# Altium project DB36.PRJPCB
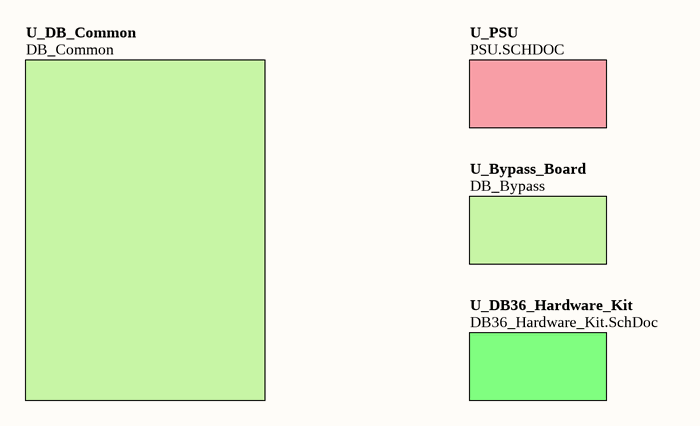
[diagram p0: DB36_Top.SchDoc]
ProjectAddress1: L3, 12A Rodborough Road; ProjectAddress2: Frenchs Forest; ProjectAddress3: NSW 2086; ProjectAddress4: Australia; ProjectAssyNum: D-820-0010; ProjectOrganization: Altium Limited; ProjectRevision: 01; ProjectTitle: DB36 - Daughter Board Virtex4; ProjectTotalSheets: 23
9 sheets, 100 parts. Net scope: hierarchical (ports join the sheet entries above them; power ports are global).
Board files: DB36.PcbDoc, DB36_Panel.PcbDoc
Sheets:
  DB36_Top.SchDoc
    U_PSU = PSU.SCHDOC
    U_DB36_Hardware_Kit = DB36_Hardware_Kit.SchDoc
  DEVICES.SchDoc
    U_FPGA = FPGA.SCHDOC
      U_FPGA_Power = FPGA_NonIO.SchDoc
      U_Bypass_3V3 = Bypass_FPGA_3V3.SchDoc
      U_Bypass_2V5 = Bypass_FPGA_2V5.SCHDOC
      U_Bypass_1V2 = Bypass_FPGA_1V2.SCHDOC

## Sheet DB36_Top.SchDoc: DB36 Top Level
size A4; Organization: Altium Limited.; Address1: Level 3, 12a Rodborough Rd; Address2: Frenchs Forest 2086; Address3: NSW; Address4: AUSTRALIA; DocumentNumber: 1; SheetNumber: 2; SheetTotal: 23

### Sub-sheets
U_Bypass_Board = DB_Bypass (file not in this document): no entries
U_DB36_Hardware_Kit = DB36_Hardware_Kit.SchDoc: no entries
U_DB_Common = DB_Common (file not in this document): no entries
U_PSU = PSU.SCHDOC: no entries

## Sheet PSU.SCHDOC: Power Supplies
size A4; Organization: Altium Limited.; Address1: Level 3, 12a Rodborough Rd; Address2: Frenchs Forest 2086; Address3: NSW; Address4: AUSTRALIA; DocumentNumber: 10; SheetNumber: 10; SheetTotal: 23
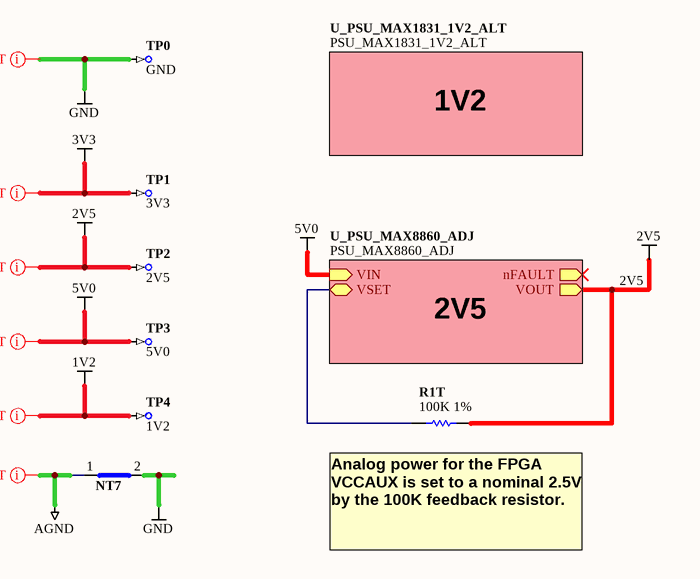
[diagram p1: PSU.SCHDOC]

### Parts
NT7  Net Tie SMT2  [NETTIE-SMT2-8X8]  (value not drawn)  (net tie, no BOM)
R1T  100K 1%  [RESC1005-STAR]
TP0  GND  [TestPin]  (no BOM)
TP1  3V3  [TestPin]  (no BOM)
TP2  2V5  [TestPin]  (no BOM)
TP3  5V0  [TestPin]  (no BOM)
TP4  1V2  [TestPin]  (no BOM)

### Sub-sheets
U_PSU_MAX1831_1V2_ALT = PSU_MAX1831_1V2_ALT (file not in this document): no entries
U_PSU_MAX8860_ADJ = PSU_MAX8860_ADJ (file not in this document): nFAULT (out), VIN (in), VOUT (out), VSET (bidir)

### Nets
1V2: TP4.1
2V5: R1T.2 TP2.1 ; sheet U_PSU_MAX8860_ADJ/VOUT
3V3: TP1.1
5V0: TP3.1 ; sheet U_PSU_MAX8860_ADJ/VIN
AGND: NT7.1(Net1)
GND: NT7.2(Net2) TP0.1
NetR1T_1: R1T.1 ; sheet U_PSU_MAX8860_ADJ/VSET

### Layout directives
net class PWRNET: 1V2, 2V5, 3V3, 5V0, AGND, GND

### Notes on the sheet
- 1V2
- 2V5
- (near R1T) Analog power for the FPGA VCCAUX is set to a nominal 2.5V by the 100K feedback resistor.

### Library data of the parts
NT7 = D-002-0002: Net-Tie, Surface Mount, 2 x 0.4mm x 0.2mm SMT Pads - For 0.2mm Track
R1T = D-100-0132: Resistor, 100K 1% 0402 (1005); Power Rating: 63 mW
TP0-TP4 = D-006-0000: Test Point, PCB Mount with Silkscreen Box

## Sheet DB36_Hardware_Kit.SchDoc: DB36 Hardware Kit
size A4; Organization: Altium Limited.; Address1: Level 3, 12a Rodborough Rd; Address2: Frenchs Forest 2086; Address3: NSW; Address4: AUSTRALIA; DocumentNumber: 9; SheetNumber: 9; SheetTotal: 23
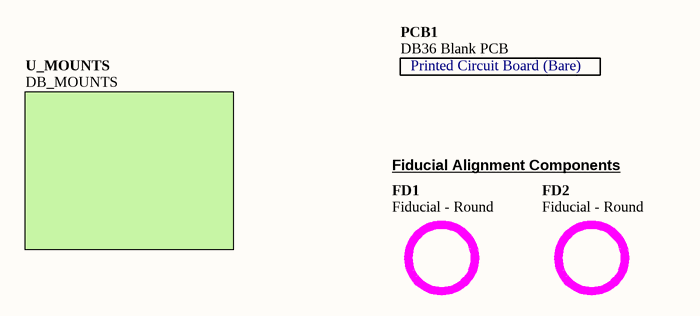
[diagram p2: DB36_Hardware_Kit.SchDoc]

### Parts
FD1  Fiducial - Round  [FIDUCIAL ROUND]
FD2  Fiducial - Round  [FIDUCIAL ROUND]
PCB1  DB36 Blank PCB  [DB36 Blank PCB]

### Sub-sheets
U_MOUNTS = DB_MOUNTS (file not in this document): no entries

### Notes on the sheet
- Fiducial Alignment Components

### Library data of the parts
FD1 FD2 = D-000-0005: Fiducial - Round 1.5mm Top-Bottom
PCB1 = D-810-0010: DB36 Blank PCB - Daughter Board Xilinx Virtex4 XC4VLX25FF668; ProjectPath: DB36.PrjPCB

## Sheet DEVICES.SchDoc: FPGA, LEDs and SRAM Memory
size A4; Organization: Altium Limited.; Address1: Level 3, 12a Rodborough Rd; Address2: Frenchs Forest 2086; Address3: NSW; Address4: AUSTRALIA; DocumentNumber: 2; SheetNumber: 3; SheetTotal: 23
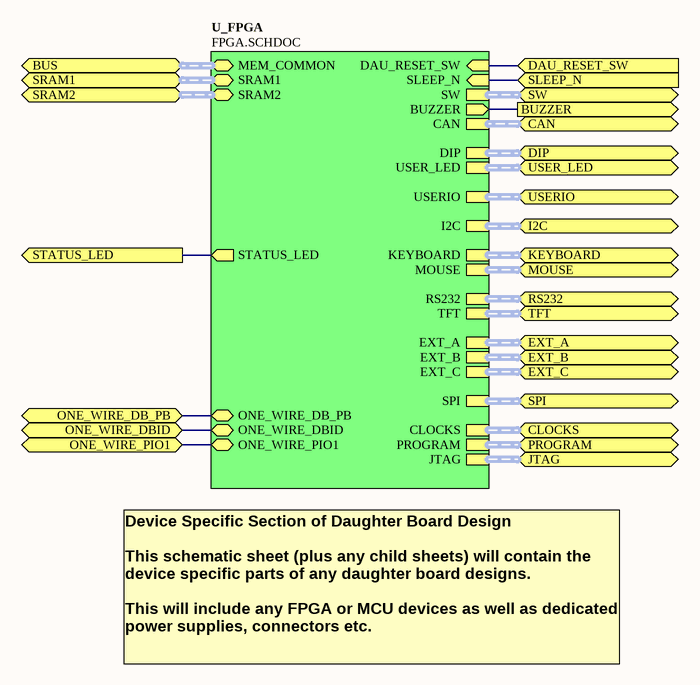
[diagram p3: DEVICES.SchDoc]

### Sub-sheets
U_FPGA = FPGA.SCHDOC: SRAM1 (harness SRAM-256Kx16), SRAM2 (harness SRAM-256Kx16), MEM_COMMON (harness HOSTMEMORY), DAU_RESET_SW (in), BUZZER (out), ONE_WIRE_DBID (bidir), ONE_WIRE_DB_PB (bidir), ONE_WIRE_PIO1 (bidir), JTAG (harness HardSoft_JTAG), SW (harness SW5), DIP (harness SW8), USERIO (harness IO36), EXT_A (harness PBIO), EXT_B (harness PBIO), EXT_C (harness PBIO), USER_LED (harness LED8), SPI (harness DAU_SPI), I2C (harness I2C), CAN (harness CAN_INT), RS232 (harness RS232_INT), KEYBOARD (harness PS2), MOUSE (harness PS2), TFT (harness DAU_TFT), PROGRAM (harness DAU_CTRL), CLOCKS (harness DAU_CLK), STATUS_LED (out), SLEEP_N (in)

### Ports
BUS (harness HOSTMEMORY), BUZZER (out), CAN, CLOCKS, DAU_RESET_SW (in), DIP, EXT_A, EXT_B, EXT_C, I2C, JTAG, KEYBOARD, MOUSE, ONE_WIRE_DB_PB (bidir), ONE_WIRE_DBID (bidir), ONE_WIRE_PIO1 (bidir), PROGRAM, RS232, SLEEP_N (in), SPI, SRAM1, SRAM2 (harness SRAM-256Kx16), STATUS_LED (out), SW, TFT, USER_LED, USERIO

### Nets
BUZZER: port BUZZER, sheet U_FPGA/BUZZER
DAU_RESET_SW: port DAU_RESET_SW, sheet U_FPGA/DAU_RESET_SW
ONE_WIRE_DB_PB: port ONE_WIRE_DB_PB, sheet U_FPGA/ONE_WIRE_DB_PB
ONE_WIRE_DBID: port ONE_WIRE_DBID, sheet U_FPGA/ONE_WIRE_DBID
ONE_WIRE_PIO1: port ONE_WIRE_PIO1, sheet U_FPGA/ONE_WIRE_PIO1
SLEEP_N: port SLEEP_N, sheet U_FPGA/SLEEP_N
STATUS_LED: port STATUS_LED, sheet U_FPGA/STATUS_LED

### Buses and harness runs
harness port BUS = sheet U_FPGA/MEM_COMMON
harness port CAN = sheet U_FPGA/CAN
harness port CLOCKS = sheet U_FPGA/CLOCKS
harness port DIP = sheet U_FPGA/DIP
harness port EXT_A = sheet U_FPGA/EXT_A
harness port EXT_B = sheet U_FPGA/EXT_B
harness port EXT_C = sheet U_FPGA/EXT_C
harness port I2C = sheet U_FPGA/I2C
harness port JTAG = sheet U_FPGA/JTAG
harness port KEYBOARD = sheet U_FPGA/KEYBOARD
harness port MOUSE = sheet U_FPGA/MOUSE
harness port PROGRAM = sheet U_FPGA/PROGRAM
harness port RS232 = sheet U_FPGA/RS232
harness port SPI = sheet U_FPGA/SPI
harness port SRAM1 = sheet U_FPGA/SRAM1
harness port SRAM2 = sheet U_FPGA/SRAM2
harness port SW = sheet U_FPGA/SW
harness port TFT = sheet U_FPGA/TFT
harness port USER_LED = sheet U_FPGA/USER_LED
harness port USERIO = sheet U_FPGA/USERIO

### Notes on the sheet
- Device Specific Section of Daughter Board Design
  This schematic sheet (plus any child sheets) will contain the device specific parts of any daughter board designs.
  This will include any FPGA or MCU devices as well as dedicated power supplies, connectors etc.

## Sheet FPGA.SCHDOC: FPGA
size A2; Organization: Altium Limited.; Address1: Level 3, 12a Rodborough Rd; Address2: Frenchs Forest 2086; Address3: NSW; Address4: AUSTRALIA; DocumentNumber: 3; SheetNumber: 4; SheetTotal: 23; PageSetup: Record=PageOptions|CenterHorizontal=True|CenterVertical=True|PrintScale=0.71|XCorrection=1.00|YCorrection=1.00|PrintKind=0|BorderSize=5000000|LeftOffset=0|BottomOffset=0|Orientation=2|PaperLength=4199|PaperWidth=2969|Scale=100|PaperSource=7|PrintQuality=600|MediaType=1|DitherType=10|PaperKind=A3 (297 x 420 mm)|PrintScaleMode=1
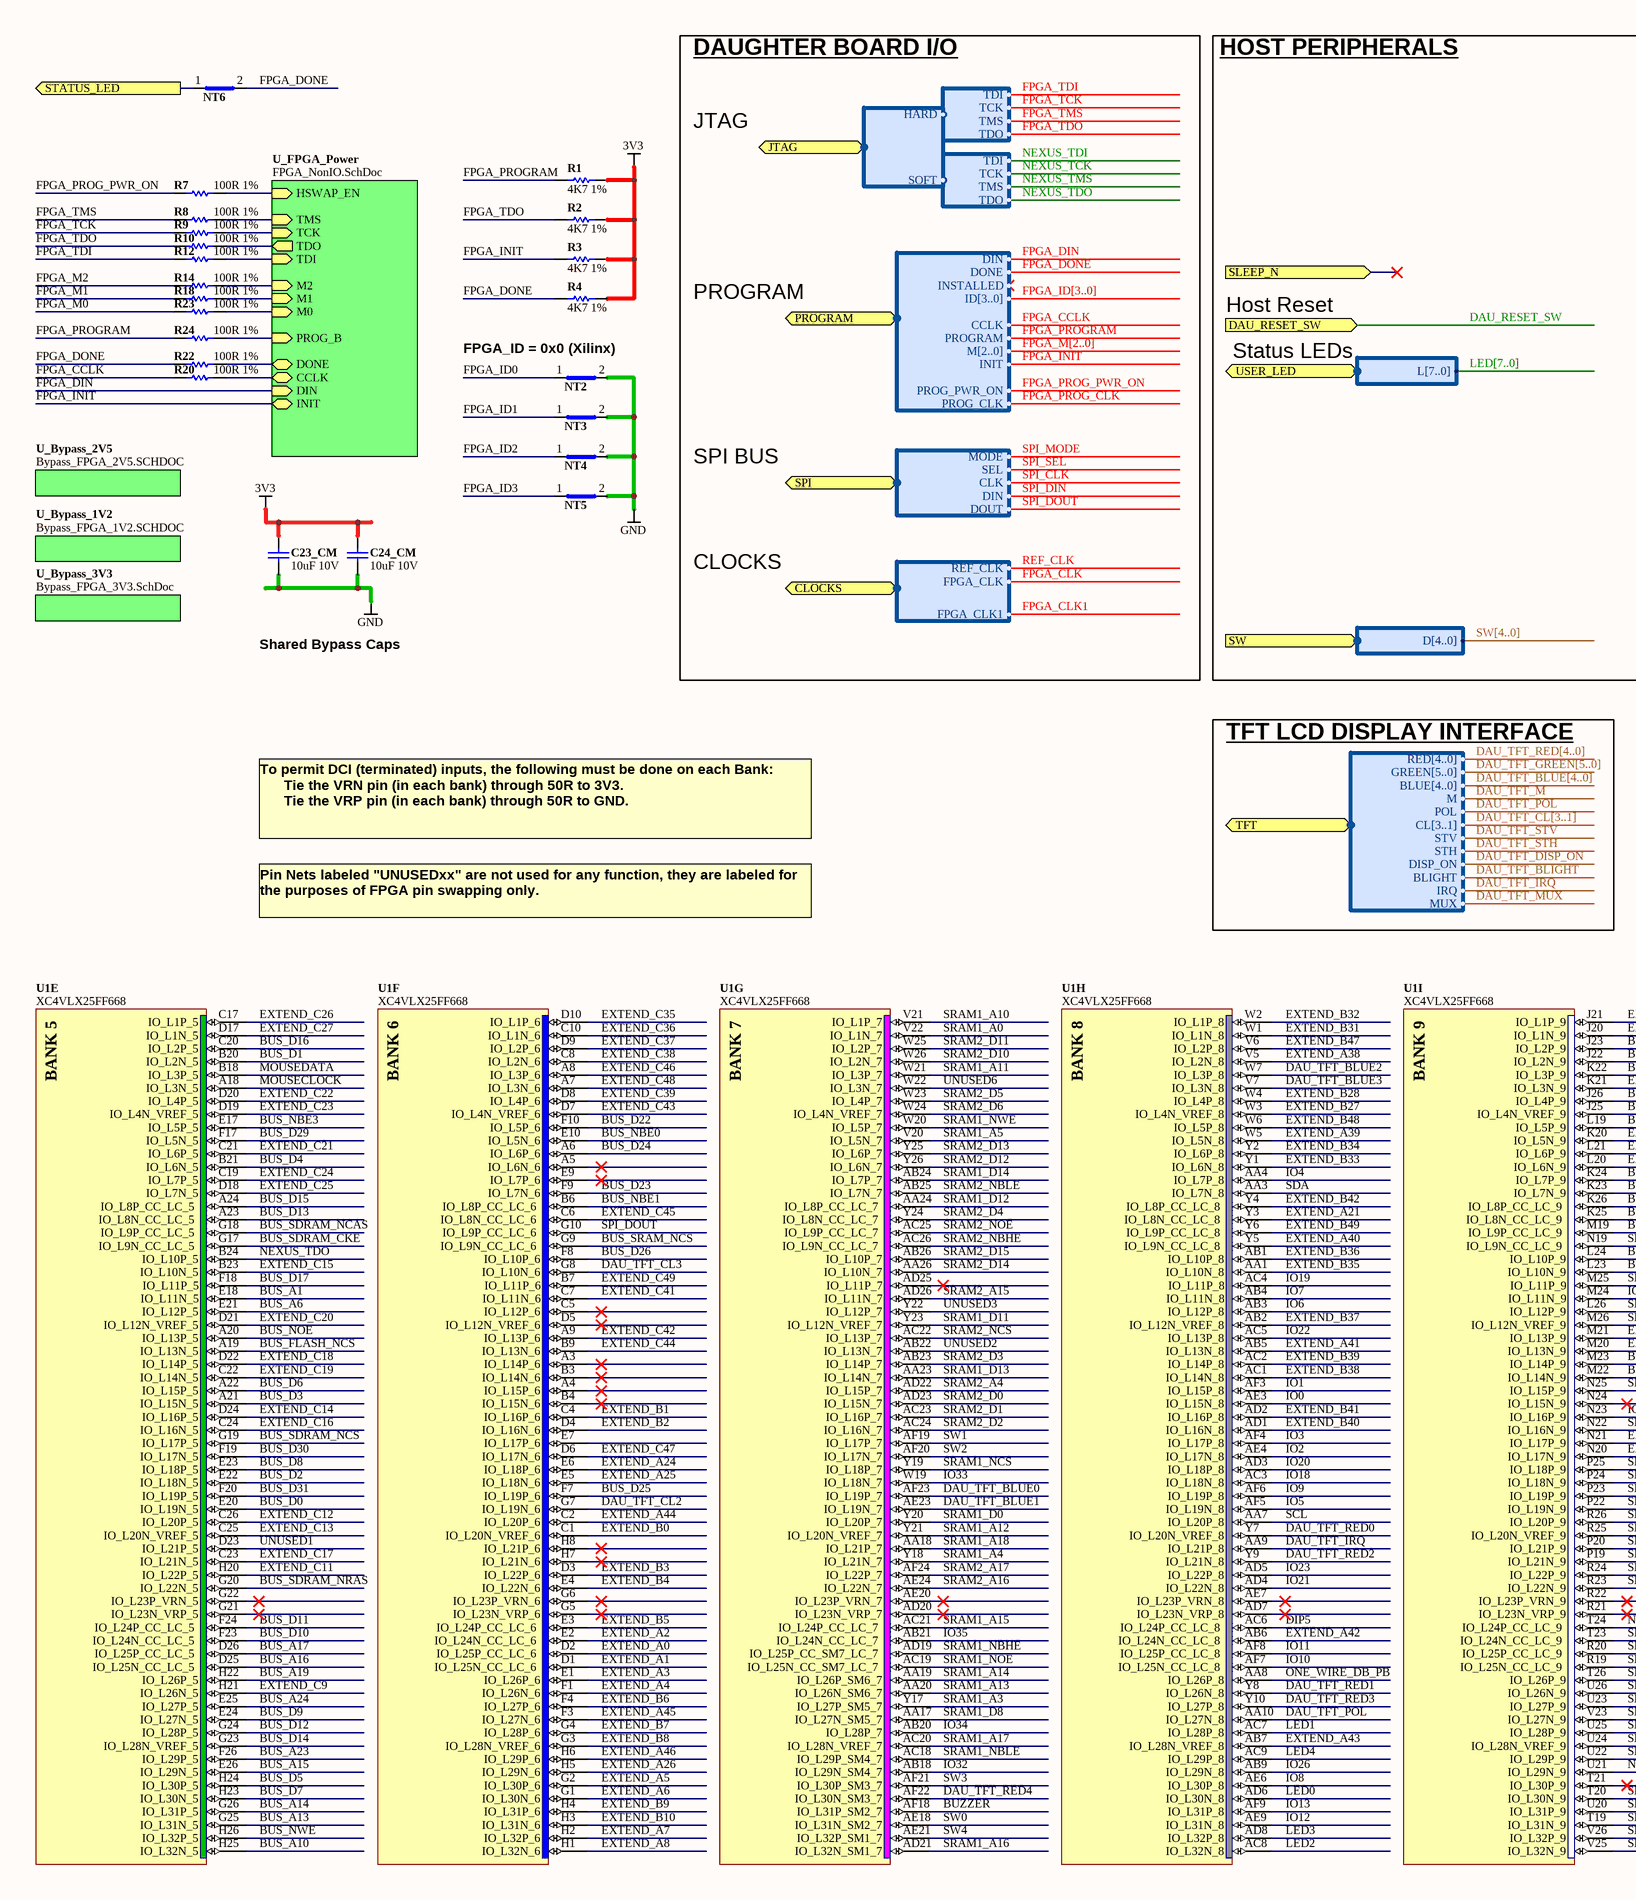
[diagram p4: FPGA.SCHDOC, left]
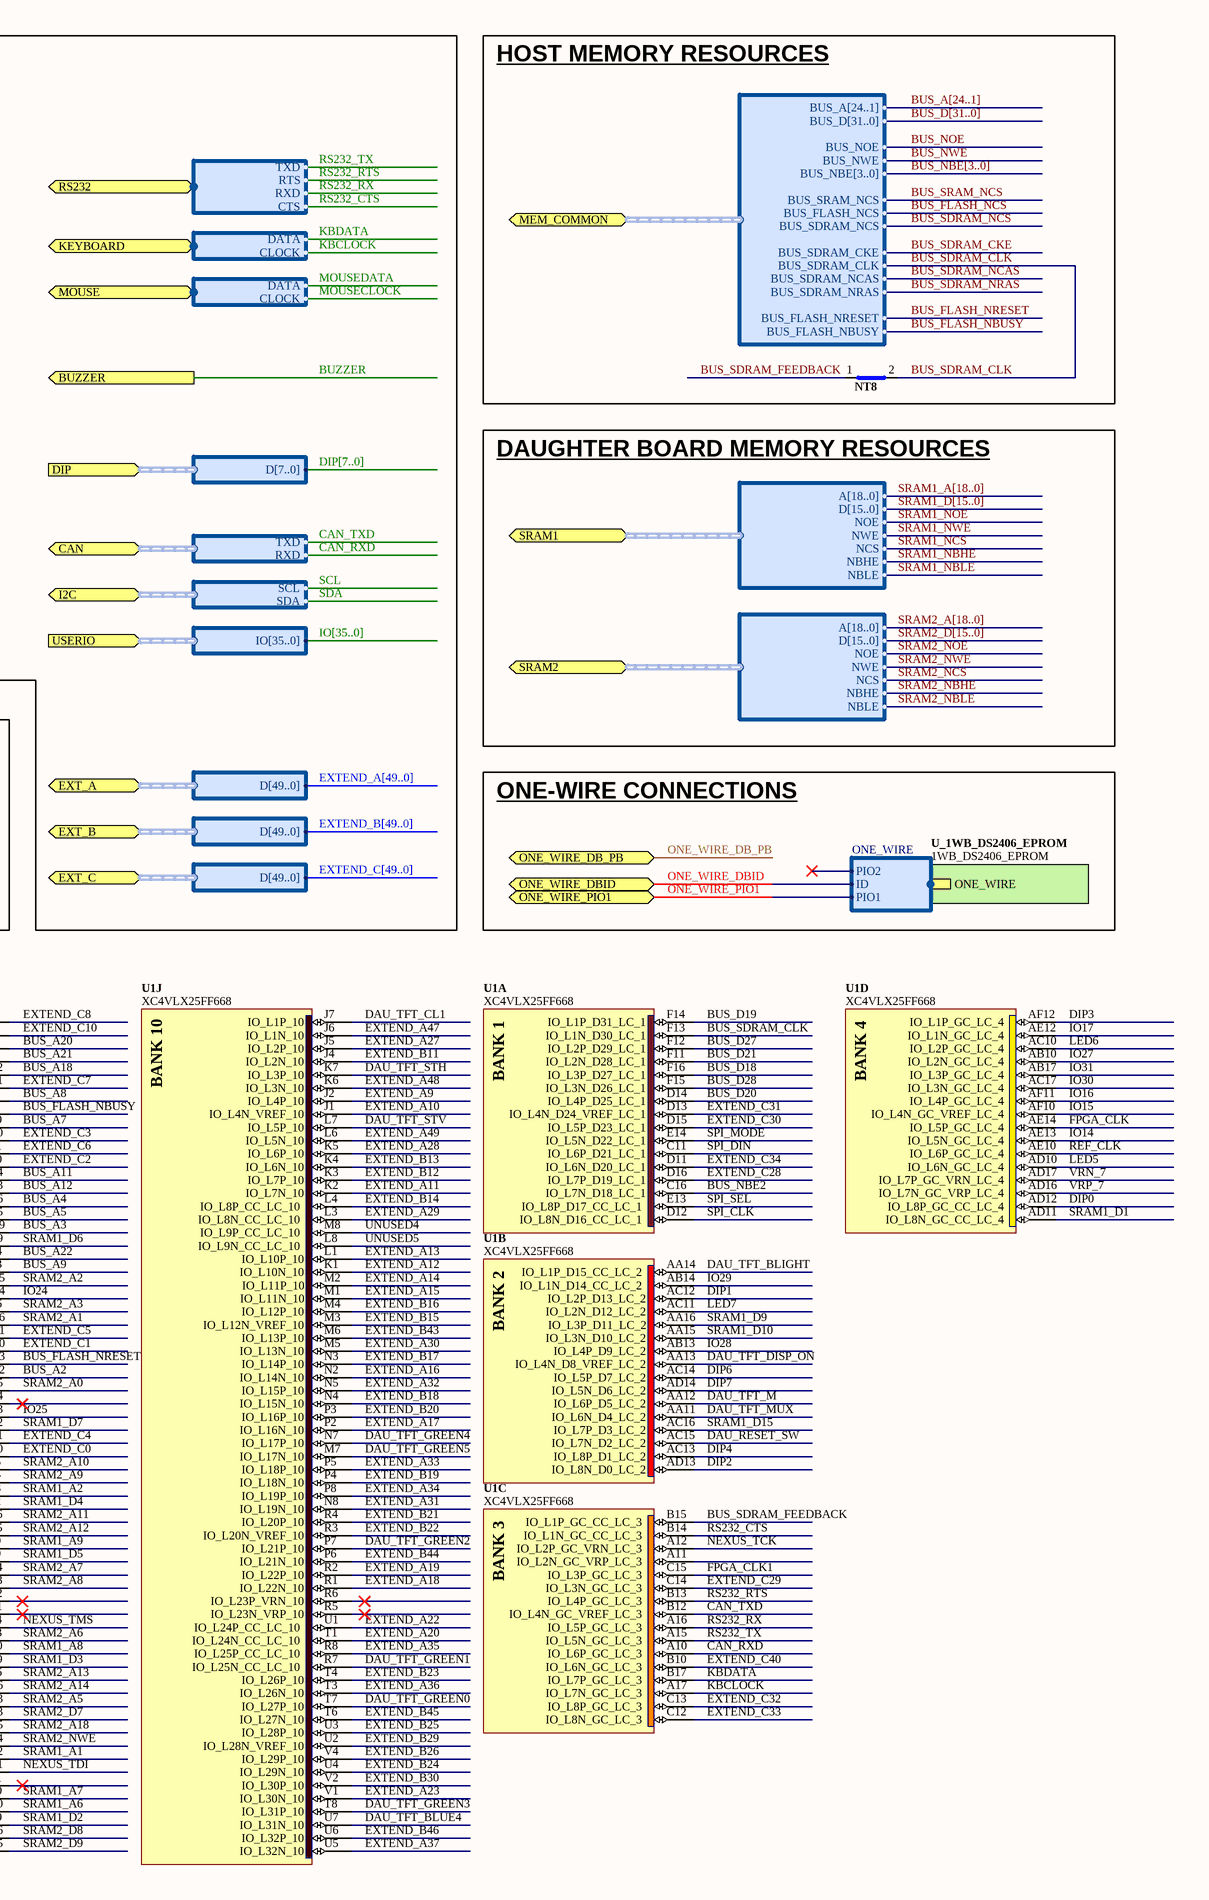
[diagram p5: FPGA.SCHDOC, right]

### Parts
C23_CM  10uF 10V  [CAPC2012-STAR]
C24_CM  10uF 10V  [CAPC2012-STAR]
NT2  Net Tie SMT2  [NETTIE-SMT2-8X8]  (value not drawn)  (net tie, no BOM)
NT3  Net Tie SMT2  [NETTIE-SMT2-8X8]  (value not drawn)  (net tie, no BOM)
NT4  Net Tie SMT2  [NETTIE-SMT2-8X8]  (value not drawn)  (net tie, no BOM)
NT5  Net Tie SMT2  [NETTIE-SMT2-8X8]  (value not drawn)  (net tie, no BOM)
NT6  Net Tie SMT2  [NETTIE-SMT2-8X8]  (value not drawn)  (net tie, no BOM)
NT8  Net Tie SMT2  [NETTIE-SMT2-8X8]  (value not drawn)  (net tie, no BOM)
R1  4K7 1%  [RESC1005-STAR]
R2  4K7 1%  [RESC1005-STAR]
R3  4K7 1%  [RESC1005-STAR]
R4  4K7 1%  [RESC1005-STAR]
R7  100R 1%  [RESC1005-STAR]
R8  100R 1%  [RESC1005-STAR]
R9  100R 1%  [RESC1005-STAR]
R10  100R 1%  [RESC1005-STAR]
R12  100R 1%  [RESC1005-STAR]
R14  100R 1%  [RESC1005-STAR]
R18  100R 1%  [RESC1005-STAR]
R20  100R 1%  [RESC1005-STAR]
R22  100R 1%  [RESC1005-STAR]
R23  100R 1%  [RESC1005-STAR]
R24  100R 1%  [RESC1005-STAR]
U1  XC4VLX25FF668  [XC4VLX25-10FF668C]  (parts A,B,C,D,E,F,G,H,I,J of 14)

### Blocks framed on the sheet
HOST MEMORY RESOURCES: NT8

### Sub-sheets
U_1WB_DS2406_EPROM = 1WB_DS2406_EPROM (file not in this document): ONE_WIRE (harness ONE_WIRE)
U_Bypass_1V2 = Bypass_FPGA_1V2.SCHDOC: no entries
U_Bypass_2V5 = Bypass_FPGA_2V5.SCHDOC: no entries
U_Bypass_3V3 = Bypass_FPGA_3V3.SchDoc: no entries
U_FPGA_Power = FPGA_NonIO.SchDoc: TMS (in), DONE (bidir), M1 (in), CCLK (bidir), M0 (in), M2 (in), TCK (in), HSWAP_EN (in), TDI (in), PROG_B (in), TDO (out), DIN (in), INIT (bidir)

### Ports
BUZZER (out), CAN (harness CAN_INT), CLOCKS (harness DAU_CLK), DAU_RESET_SW (in), DIP (harness SW8), EXT_A (harness PBIO), EXT_B (harness PBIO), EXT_C (harness PBIO), I2C (harness I2C), JTAG (harness HARDSOFT_JTAG), KEYBOARD (harness PS2), MEM_COMMON (harness HOSTMEMORY), MOUSE (harness PS2), ONE_WIRE_DB_PB (bidir), ONE_WIRE_DBID (bidir), ONE_WIRE_PIO1 (bidir), PROGRAM (harness DAU_CTRL), RS232 (harness RS232_INT), SLEEP_N (in), SPI (harness DAU_SPI), SRAM1 (harness SRAM-256Kx16), SRAM2 (harness SRAM-256Kx16), STATUS_LED (out), SW (harness SW5), TFT (harness DAU_TFT), USER_LED (harness LED8), USERIO (harness IO36)

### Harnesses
ONE_WIRE: ID, PIO1, PIO2
SRAM-256Kx16: A[18..0], D[15..0], NCS, NWE, NOE, NBHE, NBLE
HOSTMEMORY: BUS_A[24..1], BUS_D[31..0], BUS_NOE, BUS_NWE, BUS_NBE[3..0], BUS_SRAM_NCS, BUS_FLASH_NCS, BUS_SDRAM_NCS, BUS_SDRAM_CKE, BUS_SDRAM_CLK, BUS_SDRAM_NCAS, BUS_SDRAM_NRAS, BUS_FLASH_NRESET, BUS_FLASH_NBUSY
DAU_CLK: REF_CLK, FPGA_CLK, FPGA_CLK1
DAU_SPI: MODE, SEL, CLK, DIN, DOUT
DAU_CTRL: DIN, DONE, INSTALLED, ID[3..0], CCLK, PROGRAM, M[2..0], INIT, PROG_PWR_ON, PROG_CLK
JTAG: TMS, TDO, TDI, TCK
HARDSOFT_JTAG: HARD, SOFT
LED8: L[7..0]
SW5: D[4..0]
DAU_TFT: RED[4..0], GREEN[5..0], BLUE[4..0], M, POL, CL[3..1], STV, STH, DISP_ON, BLIGHT, IRQ, MUX
PS2: DATA, CLOCK
RS232_INT: RXD, TXD, RTS, CTS
IO36: IO[35..0]
SW8: D[7..0]
CAN_INT: TXD, RXD
I2C: SCL, SDA
PBIO: D[49..0]

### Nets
3V3: C23_CM.1 C24_CM.1 R1.2 R2.2 R3.2 R4.2
GND: C23_CM.2 C24_CM.2 NT2.2(Net2) NT3.2(Net2) NT4.2(Net2) NT5.2(Net2)
BUS_A1: U1.E18(IO_L11N_5)
BUS_A2: U1.M22(IO_L14N_9)
BUS_A3: U1.M19(IO_L9P_CC_LC_9)
BUS_A4: U1.K26(IO_L8P_CC_LC_9)
BUS_A5: U1.K25(IO_L8N_CC_LC_9)
BUS_A6: U1.E21(IO_L12P_5)
BUS_A7: U1.L19(IO_L5P_9)
BUS_A8: U1.J26(IO_L4P_9)
BUS_A9: U1.L23(IO_L10N_9)
BUS_A10: U1.H25(IO_L32N_5)
BUS_A11: U1.K24(IO_L7P_9)
BUS_A12: U1.K23(IO_L7N_9)
BUS_A13: U1.G25(IO_L31N_5)
BUS_A14: U1.G26(IO_L31P_5)
BUS_A15: U1.E26(IO_L29N_5)
BUS_A16: U1.D25(IO_L25N_CC_LC_5)
BUS_A17: U1.D26(IO_L25P_CC_LC_5)
BUS_A18: U1.K22(IO_L3P_9)
BUS_A19: U1.H22(IO_L26P_5)
BUS_A20: U1.J23(IO_L2P_9)
BUS_A21: U1.J22(IO_L2N_9)
BUS_A22: U1.L24(IO_L10P_9)
BUS_A23: U1.F26(IO_L29P_5)
BUS_A24: U1.E25(IO_L27P_5)
BUS_D0: U1.E20(IO_L19N_5)
BUS_D1: U1.B20(IO_L2N_5)
BUS_D2: U1.E22(IO_L18N_5)
BUS_D3: U1.A21(IO_L15N_5)
BUS_D4: U1.B21(IO_L6N_5)
BUS_D5: U1.H24(IO_L30P_5)
BUS_D6: U1.A22(IO_L15P_5)
BUS_D7: U1.H23(IO_L30N_5)
BUS_D8: U1.E23(IO_L18P_5)
BUS_D9: U1.E24(IO_L27N_5)
BUS_D10: U1.F23(IO_L24N_CC_LC_5)
BUS_D11: U1.F24(IO_L24P_CC_LC_5)
BUS_D12: U1.G24(IO_L28P_5)
BUS_D13: U1.A23(IO_L8N_CC_LC_5)
BUS_D14: U1.G23(IO_L28N_VREF_5)
BUS_D15: U1.A24(IO_L8P_CC_LC_5)
BUS_D16: U1.C20(IO_L2P_5)
BUS_D17: U1.F18(IO_L11P_5)
BUS_D18: U1.F16(IO_L3P_D27_LC_1)
BUS_D19: U1.F14(IO_L1P_D31_LC_1)
BUS_D20: U1.D14(IO_L4P_D25_LC_1)
BUS_D21: U1.F11(IO_L2N_D28_LC_1)
BUS_D22: U1.F10(IO_L5P_6)
BUS_D23: U1.F9(IO_L7N_6)
BUS_D24: U1.A6(IO_L6P_6)
BUS_D25: U1.F7(IO_L19P_6)
BUS_D26: U1.F8(IO_L10P_6)
BUS_D27: U1.F12(IO_L2P_D29_LC_1)
BUS_D28: U1.F15(IO_L3N_D26_LC_1)
BUS_D29: U1.F17(IO_L5N_5)
BUS_D30: U1.F19(IO_L17N_5)
BUS_D31: U1.F20(IO_L19P_5)
BUS_FLASH_NBUSY: U1.J25(IO_L4N_VREF_9) ; port MEM_COMMON.BUS_FLASH_NBUSY
BUS_FLASH_NCS: U1.A19(IO_L13N_5) ; port MEM_COMMON.BUS_FLASH_NCS
BUS_FLASH_NRESET: U1.M23(IO_L14P_9) ; port MEM_COMMON.BUS_FLASH_NRESET
BUS_NBE0: U1.E10(IO_L5N_6)
BUS_NBE1: U1.B6(IO_L8P_CC_LC_6)
BUS_NBE2: U1.C16(IO_L7N_D18_LC_1)
BUS_NBE3: U1.E17(IO_L5P_5)
BUS_NOE: U1.A20(IO_L13P_5) ; port MEM_COMMON.BUS_NOE
BUS_NWE: U1.H26(IO_L32P_5) ; port MEM_COMMON.BUS_NWE
BUS_SDRAM_CKE: U1.G17(IO_L9N_CC_LC_5) ; port MEM_COMMON.BUS_SDRAM_CKE
BUS_SDRAM_CLK: NT8.2(Net2) U1.F13(IO_L1N_D30_LC_1) ; port MEM_COMMON.BUS_SDRAM_CLK
BUS_SDRAM_FEEDBACK: NT8.1(Net1) U1.B15(IO_L1P_GC_CC_LC_3)
BUS_SDRAM_NCAS: U1.G18(IO_L9P_CC_LC_5) ; port MEM_COMMON.BUS_SDRAM_NCAS
BUS_SDRAM_NCS: U1.G19(IO_L17P_5) ; port MEM_COMMON.BUS_SDRAM_NCS
BUS_SDRAM_NRAS: U1.G20(IO_L22N_5) ; port MEM_COMMON.BUS_SDRAM_NRAS
BUS_SRAM_NCS: U1.G9(IO_L9N_CC_LC_6) ; port MEM_COMMON.BUS_SRAM_NCS
BUZZER: U1.AF18(IO_L31P_SM2_7) ; port BUZZER
CAN_RXD: U1.A10(IO_L6P_GC_LC_3) ; port CAN.RXD
CAN_TXD: U1.B12(IO_L4N_GC_VREF_LC_3) ; port CAN.TXD
CCLK: R20.2 ; sheet U_FPGA_Power/CCLK
DAU_RESET_SW: U1.AC15(IO_L7N_D2_LC_2) ; port DAU_RESET_SW
DAU_TFT_BLIGHT: U1.AA14(IO_L1P_D15_CC_LC_2) ; port TFT.BLIGHT
DAU_TFT_BLUE0: U1.AF23(IO_L19P_7)
DAU_TFT_BLUE1: U1.AE23(IO_L19N_7)
DAU_TFT_BLUE2: U1.W7(IO_L3P_8)
DAU_TFT_BLUE3: U1.V7(IO_L3N_8)
DAU_TFT_BLUE4: U1.U7(IO_L31N_10)
DAU_TFT_CL1: U1.J7(IO_L1P_10)
DAU_TFT_CL2: U1.G7(IO_L19N_6)
DAU_TFT_CL3: U1.G8(IO_L10N_6)
DAU_TFT_DISP_ON: U1.AA13(IO_L4N_D8_VREF_LC_2) ; port TFT.DISP_ON
DAU_TFT_GREEN0: U1.T7(IO_L27P_10)
DAU_TFT_GREEN1: U1.R7(IO_L25N_CC_LC_10)
DAU_TFT_GREEN2: U1.P7(IO_L21P_10)
DAU_TFT_GREEN3: U1.T8(IO_L31P_10)
DAU_TFT_GREEN4: U1.N7(IO_L17P_10)
DAU_TFT_GREEN5: U1.M7(IO_L17N_10)
DAU_TFT_IRQ: U1.AA9(IO_L21P_8) ; port TFT.IRQ
DAU_TFT_M: U1.AA12(IO_L6P_D5_LC_2) ; port TFT.M
DAU_TFT_MUX: U1.AA11(IO_L6N_D4_LC_2) ; port TFT.MUX
DAU_TFT_POL: U1.AA10(IO_L27N_8) ; port TFT.POL
DAU_TFT_RED0: U1.Y7(IO_L20N_VREF_8)
DAU_TFT_RED1: U1.Y8(IO_L26N_8)
DAU_TFT_RED2: U1.Y9(IO_L21N_8)
DAU_TFT_RED3: U1.Y10(IO_L27P_8)
DAU_TFT_RED4: U1.AF22(IO_L30N_SM3_7)
DAU_TFT_STH: U1.K7(IO_L3P_10) ; port TFT.STH
DAU_TFT_STV: U1.L7(IO_L5P_10) ; port TFT.STV
DIP0: U1.AD12(IO_L8P_GC_CC_LC_4)
DIP1: U1.AC12(IO_L2P_D13_LC_2)
DIP2: U1.AD13(IO_L8N_D0_LC_2)
DIP3: U1.AF12(IO_L1P_GC_LC_4)
DIP4: U1.AC13(IO_L8P_D1_LC_2)
DIP5: U1.AC6(IO_L24P_CC_LC_8)
DIP6: U1.AC14(IO_L5P_D7_LC_2)
DIP7: U1.AD14(IO_L5N_D6_LC_2)
DONE: R22.2 ; sheet U_FPGA_Power/DONE
EXTEND_A0: U1.D2(IO_L25P_CC_LC_6)
EXTEND_A1: U1.D1(IO_L25N_CC_LC_6)
EXTEND_A2: U1.E2(IO_L24N_CC_LC_6)
EXTEND_A3: U1.E1(IO_L26P_6)
EXTEND_A4: U1.F1(IO_L26N_6)
EXTEND_A5: U1.G2(IO_L30P_6)
EXTEND_A6: U1.G1(IO_L30N_6)
EXTEND_A7: U1.H2(IO_L32P_6)
EXTEND_A8: U1.H1(IO_L32N_6)
EXTEND_A9: U1.J2(IO_L4P_10)
EXTEND_A10: U1.J1(IO_L4N_VREF_10)
EXTEND_A11: U1.K2(IO_L7N_10)
EXTEND_A12: U1.K1(IO_L10N_10)
EXTEND_A13: U1.L1(IO_L10P_10)
EXTEND_A14: U1.M2(IO_L11P_10)
EXTEND_A15: U1.M1(IO_L11N_10)
EXTEND_A16: U1.N2(IO_L14N_10)
EXTEND_A17: U1.P2(IO_L16N_10)
EXTEND_A18: U1.R1(IO_L22N_10)
EXTEND_A19: U1.R2(IO_L22P_10)
EXTEND_A20: U1.T1(IO_L24N_CC_LC_10)
EXTEND_A21: U1.Y3(IO_L8N_CC_LC_8)
EXTEND_A22: U1.U1(IO_L24P_CC_LC_10)
EXTEND_A23: U1.V1(IO_L30N_10)
EXTEND_A24: U1.E6(IO_L18P_6)
EXTEND_A25: U1.E5(IO_L18N_6)
EXTEND_A26: U1.H5(IO_L29N_6)
EXTEND_A27: U1.J5(IO_L2P_10)
EXTEND_A28: U1.K5(IO_L6P_10)
EXTEND_A29: U1.L3(IO_L8N_CC_LC_10)
EXTEND_A30: U1.M5(IO_L13N_10)
EXTEND_A31: U1.N8(IO_L19N_10)
EXTEND_A32: U1.N5(IO_L15P_10)
EXTEND_A33: U1.P5(IO_L18P_10)
EXTEND_A34: U1.P8(IO_L19P_10)
EXTEND_A35: U1.R8(IO_L25P_CC_LC_10)
EXTEND_A36: U1.T3(IO_L26N_10)
EXTEND_A37: U1.U5(IO_L32N_10)
EXTEND_A38: U1.V5(IO_L2N_8)
EXTEND_A39: U1.W5(IO_L5N_8)
EXTEND_A40: U1.Y5(IO_L9N_CC_LC_8)
EXTEND_A41: U1.AB5(IO_L13N_8)
EXTEND_A42: U1.AB6(IO_L24N_CC_LC_8)
EXTEND_A43: U1.AB7(IO_L28N_VREF_8)
EXTEND_A44: U1.C2(IO_L20P_6)
EXTEND_A45: U1.F3(IO_L27N_6)
EXTEND_A46: U1.H6(IO_L29P_6)
EXTEND_A47: U1.J6(IO_L1N_10)
EXTEND_A48: U1.K6(IO_L3N_10)
EXTEND_A49: U1.L6(IO_L5N_10)
EXTEND_B0: U1.C1(IO_L20N_VREF_6)
EXTEND_B1: U1.C4(IO_L16P_6)
EXTEND_B2: U1.D4(IO_L16N_6)
EXTEND_B3: U1.D3(IO_L22P_6)
EXTEND_B4: U1.E4(IO_L22N_6)
EXTEND_B5: U1.E3(IO_L24P_CC_LC_6)
EXTEND_B6: U1.F4(IO_L27P_6)
EXTEND_B7: U1.G4(IO_L28P_6)
EXTEND_B8: U1.G3(IO_L28N_VREF_6)
EXTEND_B9: U1.H4(IO_L31P_6)
EXTEND_B10: U1.H3(IO_L31N_6)
EXTEND_B11: U1.J4(IO_L2N_10)
EXTEND_B12: U1.K3(IO_L7P_10)
EXTEND_B13: U1.K4(IO_L6N_10)
EXTEND_B14: U1.L4(IO_L8P_CC_LC_10)
EXTEND_B15: U1.M3(IO_L12N_VREF_10)
EXTEND_B16: U1.M4(IO_L12P_10)
EXTEND_B17: U1.N3(IO_L14P_10)
EXTEND_B18: U1.N4(IO_L15N_10)
EXTEND_B19: U1.P4(IO_L18N_10)
EXTEND_B20: U1.P3(IO_L16P_10)
EXTEND_B21: U1.R4(IO_L20P_10)
EXTEND_B22: U1.R3(IO_L20N_VREF_10)
EXTEND_B23: U1.T4(IO_L26P_10)
EXTEND_B24: U1.U4(IO_L29N_10)
EXTEND_B25: U1.U3(IO_L28P_10)
EXTEND_B26: U1.V4(IO_L29P_10)
EXTEND_B27: U1.W3(IO_L4N_VREF_8)
EXTEND_B28: U1.W4(IO_L4P_8)
EXTEND_B29: U1.U2(IO_L28N_VREF_10)
EXTEND_B30: U1.V2(IO_L30P_10)
EXTEND_B31: U1.W1(IO_L1N_8)
EXTEND_B32: U1.W2(IO_L1P_8)
EXTEND_B33: U1.Y1(IO_L6N_8)
EXTEND_B34: U1.Y2(IO_L6P_8)
EXTEND_B35: U1.AA1(IO_L10N_8)
EXTEND_B36: U1.AB1(IO_L10P_8)
EXTEND_B37: U1.AB2(IO_L12N_VREF_8)
EXTEND_B38: U1.AC1(IO_L14N_8)
EXTEND_B39: U1.AC2(IO_L14P_8)
EXTEND_B40: U1.AD1(IO_L16N_8)
EXTEND_B41: U1.AD2(IO_L16P_8)
EXTEND_B42: U1.Y4(IO_L8P_CC_LC_8)
EXTEND_B43: U1.M6(IO_L13P_10)
EXTEND_B44: U1.P6(IO_L21N_10)
EXTEND_B45: U1.T6(IO_L27N_10)
EXTEND_B46: U1.U6(IO_L32P_10)
EXTEND_B47: U1.V6(IO_L2P_8)
EXTEND_B48: U1.W6(IO_L5P_8)
EXTEND_B49: U1.Y6(IO_L9P_CC_LC_8)
EXTEND_C0: U1.N20(IO_L17N_9)
EXTEND_C1: U1.M20(IO_L13N_9)
EXTEND_C2: U1.L20(IO_L6N_9)
EXTEND_C3: U1.K20(IO_L5N_9)
EXTEND_C4: U1.N21(IO_L17P_9)
EXTEND_C5: U1.M21(IO_L13P_9)
EXTEND_C6: U1.L21(IO_L6P_9)
EXTEND_C7: U1.K21(IO_L3N_9)
EXTEND_C8: U1.J21(IO_L1P_9)
EXTEND_C9: U1.H21(IO_L26N_5)
EXTEND_C10: U1.J20(IO_L1N_9)
EXTEND_C11: U1.H20(IO_L22P_5)
EXTEND_C12: U1.C26(IO_L20P_5)
EXTEND_C13: U1.C25(IO_L20N_VREF_5)
EXTEND_C14: U1.D24(IO_L16P_5)
EXTEND_C15: U1.B23(IO_L10N_5)
EXTEND_C16: U1.C24(IO_L16N_5)
EXTEND_C17: U1.C23(IO_L21N_5)
EXTEND_C18: U1.D22(IO_L14P_5)
EXTEND_C19: U1.C22(IO_L14N_5)
EXTEND_C20: U1.D21(IO_L12N_VREF_5)
EXTEND_C21: U1.C21(IO_L6P_5)
EXTEND_C22: U1.D20(IO_L4P_5)
EXTEND_C23: U1.D19(IO_L4N_VREF_5)
EXTEND_C24: U1.C19(IO_L7P_5)
EXTEND_C25: U1.D18(IO_L7N_5)
EXTEND_C26: U1.C17(IO_L1P_5)
EXTEND_C27: U1.D17(IO_L1N_5)
EXTEND_C28: U1.D16(IO_L7P_D19_LC_1)
EXTEND_C29: U1.C14(IO_L3N_GC_LC_3)
EXTEND_C30: U1.D15(IO_L5P_D23_LC_1)
EXTEND_C31: U1.D13(IO_L4N_D24_VREF_LC_1)
EXTEND_C32: U1.C13(IO_L8P_GC_LC_3)
EXTEND_C33: U1.C12(IO_L8N_GC_LC_3)
EXTEND_C34: U1.D11(IO_L6N_D20_LC_1)
EXTEND_C35: U1.D10(IO_L1P_6)
EXTEND_C36: U1.C10(IO_L1N_6)
EXTEND_C37: U1.D9(IO_L2P_6)
EXTEND_C38: U1.C8(IO_L2N_6)
EXTEND_C39: U1.D8(IO_L4P_6)
EXTEND_C40: U1.B10(IO_L6N_GC_LC_3)
EXTEND_C41: U1.C7(IO_L11N_6)
EXTEND_C42: U1.A9(IO_L13P_6)
EXTEND_C43: U1.D7(IO_L4N_VREF_6)
EXTEND_C44: U1.B9(IO_L13N_6)
EXTEND_C45: U1.C6(IO_L8N_CC_LC_6)
EXTEND_C46: U1.A8(IO_L3P_6)
EXTEND_C47: U1.D6(IO_L17N_6)
EXTEND_C48: U1.A7(IO_L3N_6)
EXTEND_C49: U1.B7(IO_L11P_6)
FPGA_CCLK: R20.1 ; port PROGRAM.CCLK
FPGA_CLK: U1.AE14(IO_L5P_GC_LC_4) ; port CLOCKS.FPGA_CLK
FPGA_CLK1: U1.C15(IO_L3P_GC_LC_3) ; port CLOCKS.FPGA_CLK1
FPGA_DIN: sheet U_FPGA_Power/DIN, port PROGRAM.DIN
FPGA_DONE: NT6.2(Net2) R4.1 R22.1 ; port PROGRAM.DONE
FPGA_ID0: NT2.1(Net1)
FPGA_ID1: NT3.1(Net1)
FPGA_ID2: NT4.1(Net1)
FPGA_ID3: NT5.1(Net1)
FPGA_INIT: R3.1 ; sheet U_FPGA_Power/INIT, port PROGRAM.INIT
FPGA_M0: R23.1
FPGA_M1: R18.1
FPGA_M2: R14.1
FPGA_PROG_PWR_ON: R7.1 ; port PROGRAM.PROG_PWR_ON
FPGA_PROGRAM: R1.1 R24.1 ; port PROGRAM.PROGRAM
FPGA_TCK: R9.1 ; harness JTAG.TCK
FPGA_TDI: R12.1 ; harness JTAG.TDI
FPGA_TDO: R2.1 R10.1 ; harness JTAG.TDO
FPGA_TMS: R8.1 ; harness JTAG.TMS
HSWAP_EN: R7.2 ; sheet U_FPGA_Power/HSWAP_EN
IO0: U1.AE3(IO_L15N_8)
IO1: U1.AF3(IO_L15P_8)
IO2: U1.AE4(IO_L17N_8)
IO3: U1.AF4(IO_L17P_8)
IO4: U1.AA4(IO_L7P_8)
IO5: U1.AF5(IO_L19N_8)
IO6: U1.AB3(IO_L12P_8)
IO7: U1.AB4(IO_L11N_8)
IO8: U1.AE6(IO_L30P_8)
IO9: U1.AF6(IO_L19P_8)
IO10: U1.AF7(IO_L25N_CC_LC_8)
IO11: U1.AF8(IO_L25P_CC_LC_8)
IO12: U1.AE9(IO_L31N_8)
IO13: U1.AF9(IO_L31P_8)
IO14: U1.AE13(IO_L5N_GC_LC_4)
IO15: U1.AF10(IO_L4N_GC_VREF_LC_4)
IO16: U1.AF11(IO_L4P_GC_LC_4)
IO17: U1.AE12(IO_L1N_GC_LC_4)
IO18: U1.AC3(IO_L18N_8)
IO19: U1.AC4(IO_L11P_8)
IO20: U1.AD3(IO_L18P_8)
IO21: U1.AD4(IO_L22N_8)
IO22: U1.AC5(IO_L13P_8)
IO23: U1.AD5(IO_L22P_8)
IO24: U1.M24(IO_L11N_9)
IO25: U1.N23(IO_L16P_9)
IO26: U1.AB9(IO_L29N_8)
IO27: U1.AB10(IO_L2N_GC_LC_4)
IO28: U1.AB13(IO_L4P_D9_LC_2)
IO29: U1.AB14(IO_L1N_D14_CC_LC_2)
IO30: U1.AC17(IO_L3N_GC_LC_4)
IO31: U1.AB17(IO_L3P_GC_LC_4)
IO32: U1.AB18(IO_L29N_SM4_7)
IO33: U1.W19(IO_L18N_7)
IO34: U1.AB20(IO_L28P_7)
IO35: U1.AB21(IO_L24N_CC_LC_7)
KBCLOCK: U1.A17(IO_L7N_GC_LC_3) ; port KEYBOARD.CLOCK
KBDATA: U1.B17(IO_L7P_GC_LC_3) ; port KEYBOARD.DATA
LED0: U1.AD6(IO_L30N_8)
LED1: U1.AC7(IO_L28P_8)
LED2: U1.AC8(IO_L32N_8)
LED3: U1.AD8(IO_L32P_8)
LED4: U1.AC9(IO_L29P_8)
LED5: U1.AD10(IO_L6N_GC_LC_4)
LED6: U1.AC10(IO_L2P_GC_LC_4)
LED7: U1.AC11(IO_L2N_D12_LC_2)
M0: R23.2 ; sheet U_FPGA_Power/M0
M1: R18.2 ; sheet U_FPGA_Power/M1
M2: R14.2 ; sheet U_FPGA_Power/M2
MOUSECLOCK: U1.A18(IO_L3N_5) ; port MOUSE.CLOCK
MOUSEDATA: U1.B18(IO_L3P_5) ; port MOUSE.DATA
NEXUS_TCK: U1.A12(IO_L2P_GC_VRN_LC_3) ; harness JTAG.TCK
NEXUS_TDI: U1.U21(IO_L29N_9) ; harness JTAG.TDI
NEXUS_TDO: U1.B24(IO_L10P_5) ; harness JTAG.TDO
NEXUS_TMS: U1.T24(IO_L24P_CC_LC_9) ; harness JTAG.TMS
ONE_WIRE_DB_PB: U1.AA8(IO_L26P_8) ; port ONE_WIRE_DB_PB
ONE_WIRE_DBID: port ONE_WIRE_DBID, sheet U_1WB_DS2406_EPROM/ONE_WIRE.ID
ONE_WIRE_PIO1: port ONE_WIRE_PIO1, sheet U_1WB_DS2406_EPROM/ONE_WIRE.PIO1
PROG_B: R24.2 ; sheet U_FPGA_Power/PROG_B
REF_CLK: U1.AE10(IO_L6P_GC_LC_4) ; port CLOCKS.REF_CLK
RS232_CTS: U1.B14(IO_L1N_GC_CC_LC_3) ; port RS232.CTS
RS232_RTS: U1.B13(IO_L4P_GC_LC_3) ; port RS232.RTS
RS232_RX: U1.A16(IO_L5P_GC_LC_3) ; port RS232.RXD
RS232_TX: U1.A15(IO_L5N_GC_LC_3) ; port RS232.TXD
SCL: U1.AA7(IO_L20P_8) ; port I2C.SCL
SDA: U1.AA3(IO_L7N_8) ; port I2C.SDA
SPI_CLK: U1.D12(IO_L8N_D16_CC_LC_1) ; port SPI.CLK
SPI_DIN: U1.C11(IO_L6P_D21_LC_1) ; port SPI.DIN
SPI_DOUT: U1.G10(IO_L9P_CC_LC_6) ; port SPI.DOUT
SPI_MODE: U1.E14(IO_L5N_D22_LC_1) ; port SPI.MODE
SPI_SEL: U1.E13(IO_L8P_D17_CC_LC_1) ; port SPI.SEL
SRAM1_A0: U1.V22(IO_L1N_7)
SRAM1_A1: U1.U22(IO_L29P_9)
SRAM1_A2: U1.P23(IO_L19P_9)
SRAM1_A3: U1.Y17(IO_L27P_SM5_7)
SRAM1_A4: U1.Y18(IO_L21N_7)
SRAM1_A5: U1.V20(IO_L5N_7)
SRAM1_A6: U1.U20(IO_L31P_9)
SRAM1_A7: U1.T20(IO_L30N_9)
SRAM1_A8: U1.R20(IO_L25P_CC_LC_9)
SRAM1_A9: U1.P20(IO_L21P_9)
SRAM1_A10: U1.V21(IO_L1P_7)
SRAM1_A11: U1.W21(IO_L3P_7)
SRAM1_A12: U1.Y21(IO_L20N_VREF_7)
SRAM1_A13: U1.AA20(IO_L26N_SM6_7)
SRAM1_A14: U1.AA19(IO_L26P_SM6_7)
SRAM1_A15: U1.AC21(IO_L24P_CC_LC_7)
SRAM1_A16: U1.AD21(IO_L32N_SM1_7)
SRAM1_A17: U1.AC20(IO_L28N_VREF_7)
SRAM1_A18: U1.AA18(IO_L21P_7)
SRAM1_D0: U1.Y20(IO_L20P_7)
SRAM1_D1: U1.AD11(IO_L8N_GC_CC_LC_4)
SRAM1_D2: U1.T19(IO_L31N_9)
SRAM1_D3: U1.R19(IO_L25N_CC_LC_9)
SRAM1_D4: U1.P22(IO_L19N_9)
SRAM1_D5: U1.P19(IO_L21N_9)
SRAM1_D6: U1.N19(IO_L9N_CC_LC_9)
SRAM1_D7: U1.N22(IO_L16N_9)
SRAM1_D8: U1.AA17(IO_L27N_SM5_7)
SRAM1_D9: U1.AA16(IO_L3P_D11_LC_2)
SRAM1_D10: U1.AA15(IO_L3N_D10_LC_2)
SRAM1_D11: U1.Y23(IO_L12N_VREF_7)
SRAM1_D12: U1.AA24(IO_L8P_CC_LC_7)
SRAM1_D13: U1.AA23(IO_L14N_7)
SRAM1_D14: U1.AB24(IO_L7P_7)
SRAM1_D15: U1.AC16(IO_L7P_D3_LC_2)
SRAM1_NBHE: U1.AD19(IO_L25P_CC_SM7_LC_7) ; port SRAM1.NBHE
SRAM1_NBLE: U1.AC18(IO_L29P_SM4_7) ; port SRAM1.NBLE
SRAM1_NCS: U1.Y19(IO_L18P_7) ; port SRAM1.NCS
SRAM1_NOE: U1.AC19(IO_L25N_CC_SM7_LC_7) ; port SRAM1.NOE
SRAM1_NWE: U1.W20(IO_L5P_7) ; port SRAM1.NWE
SRAM2_A0: U1.N25(IO_L15P_9)
SRAM2_A1: U1.M26(IO_L12N_VREF_9)
SRAM2_A2: U1.M25(IO_L11P_9)
SRAM2_A3: U1.L26(IO_L12P_9)
SRAM2_A4: U1.AD22(IO_L15P_7)
SRAM2_A5: U1.U23(IO_L27P_9)
SRAM2_A6: U1.T23(IO_L24N_CC_LC_9)
SRAM2_A7: U1.R24(IO_L22P_9)
SRAM2_A8: U1.R23(IO_L22N_9)
SRAM2_A9: U1.P24(IO_L18N_9)
SRAM2_A10: U1.P25(IO_L18P_9)
SRAM2_A11: U1.R26(IO_L20P_9)
SRAM2_A12: U1.R25(IO_L20N_VREF_9)
SRAM2_A13: U1.T26(IO_L26P_9)
SRAM2_A14: U1.U26(IO_L26N_9)
SRAM2_A15: U1.AD26(IO_L11N_7)
SRAM2_A16: U1.AE24(IO_L22N_7)
SRAM2_A17: U1.AF24(IO_L22P_7)
SRAM2_A18: U1.U25(IO_L28P_9)
SRAM2_D0: U1.AD23(IO_L15N_7)
SRAM2_D1: U1.AC23(IO_L16P_7)
SRAM2_D2: U1.AC24(IO_L16N_7)
SRAM2_D3: U1.AB23(IO_L14P_7)
SRAM2_D4: U1.Y24(IO_L8N_CC_LC_7)
SRAM2_D5: U1.W23(IO_L4P_7)
SRAM2_D6: U1.W24(IO_L4N_VREF_7)
SRAM2_D7: U1.V23(IO_L27N_9)
SRAM2_D8: U1.V26(IO_L32P_9)
SRAM2_D9: U1.V25(IO_L32N_9)
SRAM2_D10: U1.W26(IO_L2N_7)
SRAM2_D11: U1.W25(IO_L2P_7)
SRAM2_D12: U1.Y26(IO_L6N_7)
SRAM2_D13: U1.Y25(IO_L6P_7)
SRAM2_D14: U1.AA26(IO_L10N_7)
SRAM2_D15: U1.AB26(IO_L10P_7)
SRAM2_NBHE: U1.AC26(IO_L9N_CC_LC_7) ; port SRAM2.NBHE
SRAM2_NBLE: U1.AB25(IO_L7N_7) ; port SRAM2.NBLE
SRAM2_NCS: U1.AC22(IO_L13P_7) ; port SRAM2.NCS
SRAM2_NOE: U1.AC25(IO_L9P_CC_LC_7) ; port SRAM2.NOE
SRAM2_NWE: U1.U24(IO_L28N_VREF_9) ; port SRAM2.NWE
STATUS_LED: NT6.1(Net1) ; port STATUS_LED
SW0: U1.AE18(IO_L31N_SM2_7)
SW1: U1.AF19(IO_L17P_7)
SW2: U1.AF20(IO_L17N_7)
SW3: U1.AF21(IO_L30P_SM3_7)
SW4: U1.AE21(IO_L32P_SM1_7)
TCK: R9.2 ; sheet U_FPGA_Power/TCK
TDI: R12.2 ; sheet U_FPGA_Power/TDI
TDO: R10.2 ; sheet U_FPGA_Power/TDO
TMS: R8.2 ; sheet U_FPGA_Power/TMS
UNUSED1: U1.D23(IO_L21P_5)
UNUSED2: U1.AB22(IO_L13N_7)
UNUSED3: U1.Y22(IO_L12P_7)
UNUSED4: U1.M8(IO_L9P_CC_LC_10)
UNUSED5: U1.L8(IO_L9N_CC_LC_10)
UNUSED6: U1.W22(IO_L3N_7)
VRN_7: U1.AD17(IO_L7P_GC_VRN_LC_4)
VRP_7: U1.AD16(IO_L7N_GC_VRP_LC_4)

Not connected (* = marked no-connect by the designer): U1 A3(IO_L14P_6)* A4(IO_L15P_6)* A5(IO_L6N_6)* A11(IO_L2N_GC_VRP_LC_3) AD7(IO_L23N_VRP_8)* AD20(IO_L23N_VRP_7)* AD25(IO_L11P_7)* AE7(IO_L23P_VRN_8)* AE20(IO_L23P_VRN_7)* B3(IO_L14N_6)* B4(IO_L15N_6)* C5(IO_L12P_6)* D5(IO_L12N_VREF_6)* E7(IO_L17P_6) E9(IO_L7P_6)* G5(IO_L23N_VRP_6)* G6(IO_L23P_VRN_6)* G21(IO_L23N_VRP_5)* G22(IO_L23P_VRN_5)* H7(IO_L21N_6)* H8(IO_L21P_6)* N24(IO_L15N_9)* R5(IO_L23N_VRP_10)* R6(IO_L23P_VRN_10)* R21(IO_L23N_VRP_9)* R22(IO_L23P_VRN_9)* T21(IO_L30P_9)*

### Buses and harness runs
bus BUS_A[24..1]
bus BUS_D[31..0]
bus BUS_NBE[3..0]
bus DAU_TFT_BLUE[4..0]
bus DAU_TFT_CL[3..1]
bus DAU_TFT_GREEN[5..0]
bus DAU_TFT_RED[4..0]
bus DIP[7..0]
bus EXTEND_A[49..0]
bus EXTEND_B[49..0]
bus EXTEND_C[49..0]
bus FPGA_ID[3..0]
bus FPGA_M[2..0]
bus IO[35..0]
bus LED[7..0]
bus SRAM1_A[18..0]
bus SRAM1_D[15..0]
bus SRAM2_A[18..0]
bus SRAM2_D[15..0]
bus SW[4..0]

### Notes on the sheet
- DAUGHTER BOARD I/O
- HOST PERIPHERALS
- JTAG
- (near NT2) FPGA_ID = 0x0
- (near NT2) (Xilinx)
- PROGRAM
- Host Reset
- Status LEDs
- SPI BUS
- DAUGHTER BOARD MEMORY RESOURCES
- CLOCKS
- Shared Bypass Caps
- TFT LCD DISPLAY INTERFACE
- ONE-WIRE CONNECTIONS
- To permit DCI (terminated) inputs, the following must be done on each Bank:
  Tie the VRN pin (in each bank) through 50R to 3V3.
  Tie the VRP pin (in each bank) through 50R to GND.
- Pin Nets labeled "UNUSEDxx" are not used for any function, they are labeled for the purposes of FPGA pin swapping only.

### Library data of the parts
C23_CM C24_CM = D-101-0087: Capacitor, Ceramic, 10uF 10% 10V 0805 (2012) X5R; Polarity: Non-Polarized
NT2-NT6 NT8 = D-002-0002: as NT7 on sheet PSU
R1-R4 = D-100-0088: Resistor, 4K7 1% 0402 (1005); Power Rating: 63 mW; Resistance: 4.7 K
R7-R10 R12 R14 R18 R20 R22-R24 = D-100-0131: Resistor, 100R 1% 0402 (1005); Power Rating: 63 mW
U1 = D-241-0007: FPGA, Xilinx Virtex-4, XC4VLX25; Supply Voltage: mV

## Sheet FPGA_NonIO.SchDoc: FPGA Power & Programming
size A4; DocumentNumber: 8; SheetNumber: 8; SheetTotal: 23; Organization: Altium Limited.; Address1: Level 3, 12a Rodborough Rd; Address2: Frenchs Forest 2086; Address3: NSW; Address4: AUSTRALIA
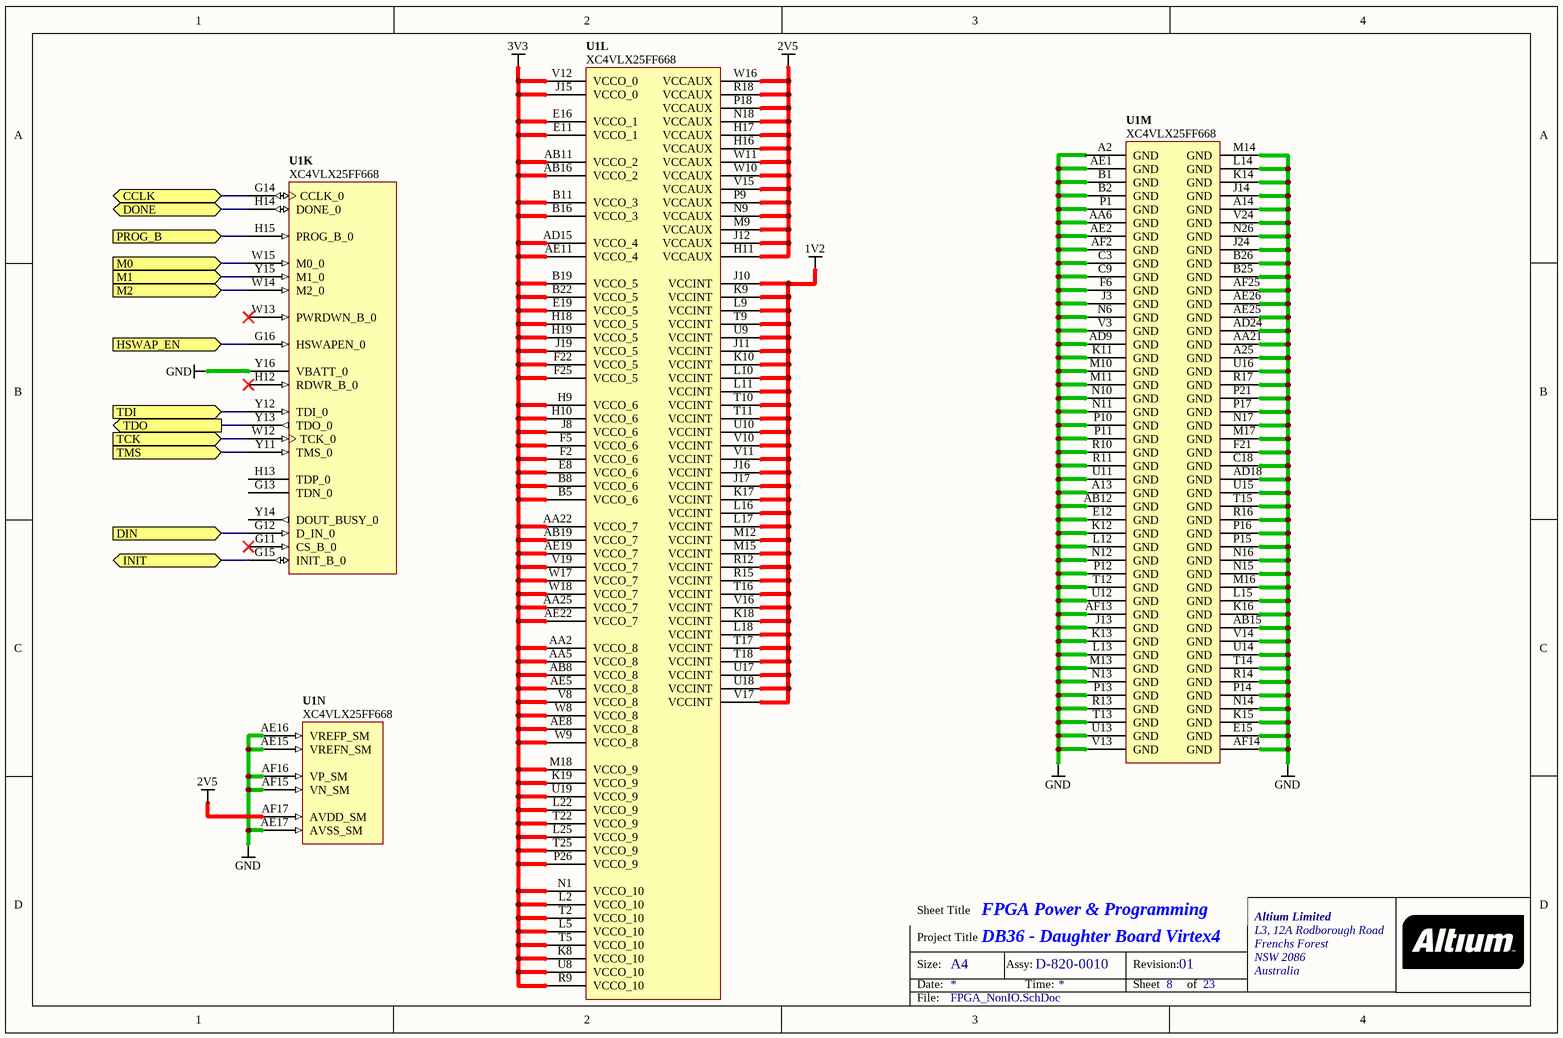
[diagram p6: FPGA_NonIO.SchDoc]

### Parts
U1  XC4VLX25FF668  [XC4VLX25-10FF668C]  (parts K,L,M,N of 14)

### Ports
CCLK (bidir), DIN (in), DONE (bidir), HSWAP_EN (in), INIT (bidir), M0 (in), M1 (in), M2 (in), PROG_B (in), TCK (in), TDI (in), TDO (out), TMS (in)

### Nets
1V2: U1.J10(VCCINT) U1.J11(VCCINT) U1.J16(VCCINT) U1.J17(VCCINT) U1.K9(VCCINT) U1.K10(VCCINT) U1.K17(VCCINT) U1.K18(VCCINT) U1.L9(VCCINT) U1.L10(VCCINT) U1.L11(VCCINT) U1.L16(VCCINT) U1.L17(VCCINT) U1.L18(VCCINT) U1.M12(VCCINT) U1.M15(VCCINT) U1.R12(VCCINT) U1.R15(VCCINT) U1.T9(VCCINT) U1.T10(VCCINT) U1.T11(VCCINT) U1.T16(VCCINT) U1.T17(VCCINT) U1.T18(VCCINT) U1.U9(VCCINT) U1.U10(VCCINT) U1.U17(VCCINT) U1.U18(VCCINT) U1.V10(VCCINT) U1.V11(VCCINT) U1.V16(VCCINT) U1.V17(VCCINT)
2V5: U1.AF17(AVDD_SM) U1.H11(VCCAUX) U1.H16(VCCAUX) U1.H17(VCCAUX) U1.J12(VCCAUX) U1.M9(VCCAUX) U1.N9(VCCAUX) U1.N18(VCCAUX) U1.P9(VCCAUX) U1.P18(VCCAUX) U1.R18(VCCAUX) U1.V15(VCCAUX) U1.W10(VCCAUX) U1.W11(VCCAUX) U1.W16(VCCAUX)
3V3: U1.AA2(VCCO_8) U1.AA5(VCCO_8) U1.AA22(VCCO_7) U1.AA25(VCCO_7) U1.AB8(VCCO_8) U1.AB11(VCCO_2) U1.AB16(VCCO_2) U1.AB19(VCCO_7) U1.AD15(VCCO_4) U1.AE5(VCCO_8) U1.AE8(VCCO_8) U1.AE11(VCCO_4) U1.AE19(VCCO_7) U1.AE22(VCCO_7) U1.B5(VCCO_6) U1.B8(VCCO_6) U1.B11(VCCO_3) U1.B16(VCCO_3) U1.B19(VCCO_5) U1.B22(VCCO_5) U1.E8(VCCO_6) U1.E11(VCCO_1) U1.E16(VCCO_1) U1.E19(VCCO_5) U1.F2(VCCO_6) U1.F5(VCCO_6) U1.F22(VCCO_5) U1.F25(VCCO_5) U1.H9(VCCO_6) U1.H10(VCCO_6) U1.H18(VCCO_5) U1.H19(VCCO_5) U1.J8(VCCO_6) U1.J15(VCCO_0) U1.J19(VCCO_5) U1.K8(VCCO_10) U1.K19(VCCO_9) U1.L2(VCCO_10) U1.L5(VCCO_10) U1.L22(VCCO_9) U1.L25(VCCO_9) U1.M18(VCCO_9) U1.N1(VCCO_10) U1.P26(VCCO_9) U1.R9(VCCO_10) U1.T2(VCCO_10) U1.T5(VCCO_10) U1.T22(VCCO_9) U1.T25(VCCO_9) U1.U8(VCCO_10) U1.U19(VCCO_9) U1.V8(VCCO_8) U1.V12(VCCO_0) U1.V19(VCCO_7) U1.W8(VCCO_8) U1.W9(VCCO_8) U1.W17(VCCO_7) U1.W18(VCCO_7)
GND: U1.A2(GND) U1.A13(GND) U1.A14(GND) U1.A25(GND) U1.AA6(GND) U1.AA21(GND) U1.AB12(GND) U1.AB15(GND) U1.AD9(GND) U1.AD18(GND) U1.AD24(GND) U1.AE1(GND) U1.AE2(GND) U1.AE15(VREFN_SM) U1.AE16(VREFP_SM) U1.AE17(AVSS_SM) U1.AE25(GND) U1.AE26(GND) U1.AF2(GND) U1.AF13(GND) U1.AF14(GND) U1.AF15(VN_SM) U1.AF16(VP_SM) U1.AF25(GND) U1.B1(GND) U1.B2(GND) U1.B25(GND) U1.B26(GND) U1.C3(GND) U1.C9(GND) U1.C18(GND) U1.E12(GND) U1.E15(GND) U1.F6(GND) U1.F21(GND) U1.J3(GND) U1.J13(GND) U1.J14(GND) U1.J24(GND) U1.K11(GND) U1.K12(GND) U1.K13(GND) U1.K14(GND) U1.K15(GND) U1.K16(GND) U1.L12(GND) U1.L13(GND) U1.L14(GND) U1.L15(GND) U1.M10(GND) U1.M11(GND) U1.M13(GND) U1.M14(GND) U1.M16(GND) U1.M17(GND) U1.N6(GND) U1.N10(GND) U1.N11(GND) U1.N12(GND) U1.N13(GND) U1.N14(GND) U1.N15(GND) U1.N16(GND) U1.N17(GND) U1.N26(GND) U1.P1(GND) U1.P10(GND) U1.P11(GND) U1.P12(GND) U1.P13(GND) U1.P14(GND) U1.P15(GND) U1.P16(GND) U1.P17(GND) U1.P21(GND) U1.R10(GND) U1.R11(GND) U1.R13(GND) U1.R14(GND) U1.R16(GND) U1.R17(GND) U1.T12(GND) U1.T13(GND) U1.T14(GND) U1.T15(GND) U1.U11(GND) U1.U12(GND) U1.U13(GND) U1.U14(GND) U1.U15(GND) U1.U16(GND) U1.V3(GND) U1.V13(GND) U1.V14(GND) U1.V24(GND) U1.Y16(VBATT_0)
CCLK: U1.G14(CCLK_0) ; port CCLK
DONE: U1.H14(DONE_0) ; port DONE
FPGA_DIN: U1.G12(D_IN_0) ; port DIN
FPGA_INIT: U1.G15(INIT_B_0) ; port INIT
HSWAP_EN: U1.G16(HSWAPEN_0) ; port HSWAP_EN
M0: U1.W15(M0_0) ; port M0
M1: U1.Y15(M1_0) ; port M1
M2: U1.W14(M2_0) ; port M2
PROG_B: U1.H15(PROG_B_0) ; port PROG_B
TCK: U1.W12(TCK_0) ; port TCK
TDI: U1.Y12(TDI_0) ; port TDI
TDO: U1.Y13(TDO_0) ; port TDO
TMS: U1.Y11(TMS_0) ; port TMS

Not connected (* = marked no-connect by the designer): U1 G11(CS_B_0)* G13(TDN_0) H12(RDWR_B_0)* H13(TDP_0) W13(PWRDWN_B_0)* Y14(DOUT_BUSY_0)

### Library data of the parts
U1 = D-241-0007: as U1 on sheet FPGA

## Sheet Bypass_FPGA_3V3.SchDoc: FPGA Bypass Capacitors for 3V3
size A4; Organization: Altium Limited.; Address1: Level 3, 12a Rodborough Rd; Address2: Frenchs Forest 2086; Address3: NSW; Address4: AUSTRALIA; DocumentNumber: 7; SheetNumber: 7; SheetTotal: 23
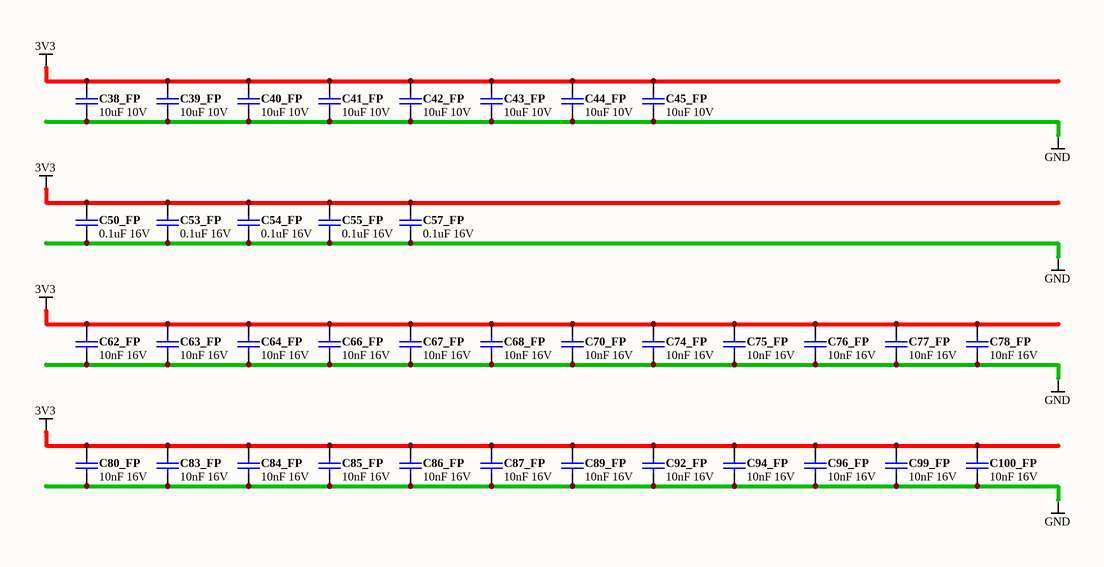
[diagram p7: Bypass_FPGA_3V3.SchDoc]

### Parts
C38_FP  10uF 10V  [CAPC2012-STAR]
C39_FP  10uF 10V  [CAPC2012-STAR]
C40_FP  10uF 10V  [CAPC2012-STAR]
C41_FP  10uF 10V  [CAPC2012-STAR]
C42_FP  10uF 10V  [CAPC2012-STAR]
C43_FP  10uF 10V  [CAPC2012-STAR]
C44_FP  10uF 10V  [CAPC2012-STAR]
C45_FP  10uF 10V  [CAPC2012-STAR]
C50_FP  0.1uF 16V  [CAPC1005-STAR]
C53_FP  0.1uF 16V  [CAPC1005-STAR]
C54_FP  0.1uF 16V  [CAPC1005-STAR]
C55_FP  0.1uF 16V  [CAPC1005-STAR]
C57_FP  0.1uF 16V  [CAPC1005-STAR]
C62_FP  10nF 16V  [CAPC1005-STAR]
C63_FP  10nF 16V  [CAPC1005-STAR]
C64_FP  10nF 16V  [CAPC1005-STAR]
C66_FP  10nF 16V  [CAPC1005-STAR]
C67_FP  10nF 16V  [CAPC1005-STAR]
C68_FP  10nF 16V  [CAPC1005-STAR]
C70_FP  10nF 16V  [CAPC1005-STAR]
C74_FP  10nF 16V  [CAPC1005-STAR]
C75_FP  10nF 16V  [CAPC1005-STAR]
C76_FP  10nF 16V  [CAPC1005-STAR]
C77_FP  10nF 16V  [CAPC1005-STAR]
C78_FP  10nF 16V  [CAPC1005-STAR]
C80_FP  10nF 16V  [CAPC1005-STAR]
C83_FP  10nF 16V  [CAPC1005-STAR]
C84_FP  10nF 16V  [CAPC1005-STAR]
C85_FP  10nF 16V  [CAPC1005-STAR]
C86_FP  10nF 16V  [CAPC1005-STAR]
C87_FP  10nF 16V  [CAPC1005-STAR]
C89_FP  10nF 16V  [CAPC1005-STAR]
C92_FP  10nF 16V  [CAPC1005-STAR]
C94_FP  10nF 16V  [CAPC1005-STAR]
C96_FP  10nF 16V  [CAPC1005-STAR]
C99_FP  10nF 16V  [CAPC1005-STAR]
C100_FP  10nF 16V  [CAPC1005-STAR]

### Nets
3V3: C38_FP.1 C39_FP.1 C40_FP.1 C41_FP.1 C42_FP.1 C43_FP.1 C44_FP.1 C45_FP.1 C50_FP.1 C53_FP.1 C54_FP.1 C55_FP.1 C57_FP.1 C62_FP.1 C63_FP.1 C64_FP.1 C66_FP.1 C67_FP.1 C68_FP.1 C70_FP.1 C74_FP.1 C75_FP.1 C76_FP.1 C77_FP.1 C78_FP.1 C80_FP.1 C83_FP.1 C84_FP.1 C85_FP.1 C86_FP.1 C87_FP.1 C89_FP.1 C92_FP.1 C94_FP.1 C96_FP.1 C99_FP.1 C100_FP.1
GND: C38_FP.2 C39_FP.2 C40_FP.2 C41_FP.2 C42_FP.2 C43_FP.2 C44_FP.2 C45_FP.2 C50_FP.2 C53_FP.2 C54_FP.2 C55_FP.2 C57_FP.2 C62_FP.2 C63_FP.2 C64_FP.2 C66_FP.2 C67_FP.2 C68_FP.2 C70_FP.2 C74_FP.2 C75_FP.2 C76_FP.2 C77_FP.2 C78_FP.2 C80_FP.2 C83_FP.2 C84_FP.2 C85_FP.2 C86_FP.2 C87_FP.2 C89_FP.2 C92_FP.2 C94_FP.2 C96_FP.2 C99_FP.2 C100_FP.2

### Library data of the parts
C38_FP C39_FP C40_FP C41_FP C42_FP C43_FP C44_FP C45_FP = D-101-0087: as C23_CM on sheet FPGA
C50_FP C53_FP C54_FP C55_FP C57_FP = D-101-0080: Capacitor, Ceramic, 0.1uF 10% 16V 0402 (1005) X7R; Polarity: Non-Polarized
C62_FP C63_FP C64_FP C66_FP C67_FP C68_FP C70_FP C74_FP C75_FP C76_FP C77_FP C78_FP C80_FP C83_FP C84_FP C85_FP C86_FP C87_FP C89_FP C92_FP C94_FP C96_FP C99_FP C100_FP = D-101-0077: Capacitor, Ceramic, 10nF 10% 16V 0402 (1005) X7R; Polarity: Non-Polarized

## Sheet Bypass_FPGA_2V5.SCHDOC: FPGA Bypass Capacitors for 2V5
size A4; Organization: Altium Limited.; Address1: Level 3, 12a Rodborough Rd; Address2: Frenchs Forest 2086; Address3: NSW; Address4: AUSTRALIA; DocumentNumber: 6; SheetNumber: 6; SheetTotal: 23
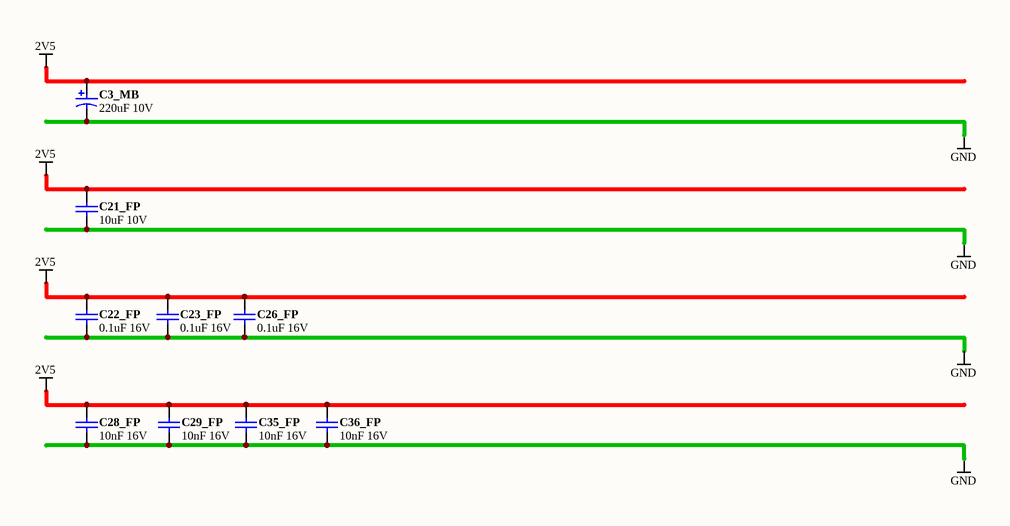
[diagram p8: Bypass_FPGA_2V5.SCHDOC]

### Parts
C3_MB  220uF 10V  [CAPC7343-STAR]
C21_FP  10uF 10V  [CAPC2012-STAR]
C22_FP  0.1uF 16V  [CAPC1005-STAR]
C23_FP  0.1uF 16V  [CAPC1005-STAR]
C26_FP  0.1uF 16V  [CAPC1005-STAR]
C28_FP  10nF 16V  [CAPC1005-STAR]
C29_FP  10nF 16V  [CAPC1005-STAR]
C35_FP  10nF 16V  [CAPC1005-STAR]
C36_FP  10nF 16V  [CAPC1005-STAR]

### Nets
2V5: C3_MB.1 C21_FP.1 C22_FP.1 C23_FP.1 C26_FP.1 C28_FP.1 C29_FP.1 C35_FP.1 C36_FP.1
GND: C3_MB.2 C21_FP.2 C22_FP.2 C23_FP.2 C26_FP.2 C28_FP.2 C29_FP.2 C35_FP.2 C36_FP.2

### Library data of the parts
C3_MB = D-101-0088: Capacitor, Tantalum, 220uF 10% 10V MCCT-D (7343-31); Polarity: Polarized
C21_FP = D-101-0087: as C23_CM on sheet FPGA
C22_FP C23_FP C26_FP = D-101-0080: as C50_FP on sheet Bypass_FPGA_3V3
C28_FP C29_FP C35_FP C36_FP = D-101-0077: as C62_FP on sheet Bypass_FPGA_3V3

## Sheet Bypass_FPGA_1V2.SCHDOC: FPGA Bypass Capacitors for 1V2
size A4; Organization: Altium Limited.; Address1: Level 3, 12a Rodborough Rd; Address2: Frenchs Forest 2086; Address3: NSW; Address4: AUSTRALIA; DocumentNumber: 5; SheetNumber: 5; SheetTotal: 23
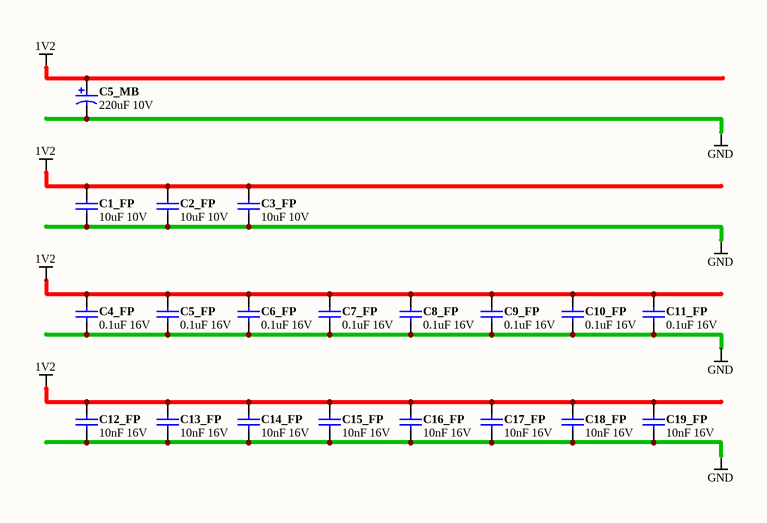
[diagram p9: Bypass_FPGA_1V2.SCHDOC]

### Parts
C1_FP  10uF 10V  [CAPC2012-STAR]
C2_FP  10uF 10V  [CAPC2012-STAR]
C3_FP  10uF 10V  [CAPC2012-STAR]
C4_FP  0.1uF 16V  [CAPC1005-STAR]
C5_FP  0.1uF 16V  [CAPC1005-STAR]
C5_MB  220uF 10V  [CAPC7343-STAR]
C6_FP  0.1uF 16V  [CAPC1005-STAR]
C7_FP  0.1uF 16V  [CAPC1005-STAR]
C8_FP  0.1uF 16V  [CAPC1005-STAR]
C9_FP  0.1uF 16V  [CAPC1005-STAR]
C10_FP  0.1uF 16V  [CAPC1005-STAR]
C11_FP  0.1uF 16V  [CAPC1005-STAR]
C12_FP  10nF 16V  [CAPC1005-STAR]
C13_FP  10nF 16V  [CAPC1005-STAR]
C14_FP  10nF 16V  [CAPC1005-STAR]
C15_FP  10nF 16V  [CAPC1005-STAR]
C16_FP  10nF 16V  [CAPC1005-STAR]
C17_FP  10nF 16V  [CAPC1005-STAR]
C18_FP  10nF 16V  [CAPC1005-STAR]
C19_FP  10nF 16V  [CAPC1005-STAR]

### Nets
1V2: C1_FP.1 C2_FP.1 C3_FP.1 C4_FP.1 C5_FP.1 C5_MB.1 C6_FP.1 C7_FP.1 C8_FP.1 C9_FP.1 C10_FP.1 C11_FP.1 C12_FP.1 C13_FP.1 C14_FP.1 C15_FP.1 C16_FP.1 C17_FP.1 C18_FP.1 C19_FP.1
GND: C1_FP.2 C2_FP.2 C3_FP.2 C4_FP.2 C5_FP.2 C5_MB.2 C6_FP.2 C7_FP.2 C8_FP.2 C9_FP.2 C10_FP.2 C11_FP.2 C12_FP.2 C13_FP.2 C14_FP.2 C15_FP.2 C16_FP.2 C17_FP.2 C18_FP.2 C19_FP.2

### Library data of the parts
C1_FP C2_FP C3_FP = D-101-0087: as C23_CM on sheet FPGA
C4_FP C5_FP C6_FP C7_FP C8_FP C9_FP C10_FP C11_FP = D-101-0080: as C50_FP on sheet Bypass_FPGA_3V3
C5_MB = D-101-0088: as C3_MB on sheet Bypass_FPGA_2V5
C12_FP C13_FP C14_FP C15_FP C16_FP C17_FP C18_FP C19_FP = D-101-0077: as C62_FP on sheet Bypass_FPGA_3V3

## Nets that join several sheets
1V2: PSU (TP4.1), FPGA_NonIO (32 pins), Bypass_FPGA_1V2 (20 pins)
2V5: PSU (R1T.2 TP2.1), FPGA_NonIO (15 pins), Bypass_FPGA_2V5 (9 pins)
3V3: PSU (TP1.1), FPGA (6 pins), FPGA_NonIO (58 pins), Bypass_FPGA_3V3 (37 pins)
GND: PSU (NT7.2 TP0.1), FPGA (6 pins), FPGA_NonIO (96 pins), Bypass_FPGA_3V3 (37 pins), Bypass_FPGA_2V5 (9 pins), Bypass_FPGA_1V2 (20 pins)
CCLK: FPGA (R20.2), FPGA_NonIO (U1.G14)
DONE: FPGA (R22.2), FPGA_NonIO (U1.H14)
FPGA_INIT: FPGA (R3.1), FPGA_NonIO (U1.G15)
HSWAP_EN: FPGA (R7.2), FPGA_NonIO (U1.G16)
M0: FPGA (R23.2), FPGA_NonIO (U1.W15)
M1: FPGA (R18.2), FPGA_NonIO (U1.Y15)
M2: FPGA (R14.2), FPGA_NonIO (U1.W14)
PROG_B: FPGA (R24.2), FPGA_NonIO (U1.H15)
TCK: FPGA (R9.2), FPGA_NonIO (U1.W12)
TDI: FPGA (R12.2), FPGA_NonIO (U1.Y12)
TDO: FPGA (R10.2), FPGA_NonIO (U1.Y13)
TMS: FPGA (R8.2), FPGA_NonIO (U1.Y11)

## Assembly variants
Production: not fitted RN1 RN2 RN3 RN4 RN5 RN6 RN7 RN8 RN17 RN18 RN19 RN20 RN21 RN22 RN23 RN24 RN25 RN26 RN27 RN28 RN29 RN30 RN31 RN32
